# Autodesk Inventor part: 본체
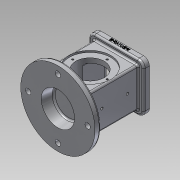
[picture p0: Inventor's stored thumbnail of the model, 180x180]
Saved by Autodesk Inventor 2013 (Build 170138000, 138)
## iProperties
Created: 2018-10
Part Number: 본체
Material: 알루미늄 6061
Document SubType Name: Modeling
Designer: hana-cad17
Density: 2.40731 g/cm^3
Mass: 877.844 g
Surface Area: 743.902 cm^2
Volume: 364.657 cm^3
Author: hana-cad17
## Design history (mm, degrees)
sketch "스케치1"
  geometry: C1 r 62.5 at (0, 0); 1 further point
  constraints: 1 centre point, 1 coincident
  dimensions: "d0" = 125 diameter of C1
extrude "돌출1" new body sketch "스케치1" distance "d1" = 10; taper "d2" = 0 deg
sketch "스케치2"
  geometry: L1 (37, 33)-(-37, 33); L2 (-37, 33)-(-37, -33); L3 (-37, -33)-(37, -33); L4 (37, -33)-(37, 33); L5 (37, 33)-(-37, -33); L6 (-37, 33)-(37, -33); C1 r 62.5 at (0, 0) reference
  constraints: 12 end point, 2 midpoint, 2 parallel, 1 horizontal, 1 perpendicular
  dimensions: "d5" = 66 distance of L3.end L1.start; "d6" = 74 distance of L1.start L1.end
extrude "돌출2" join sketch "스케치2" distance "d7" = 88; taper "d8" = 0 deg
sketch "스케치3"
  geometry: L1 (-46, 41)-(46, 41); L2 (46, 41)-(46, -41); L3 (46, -41)-(-46, -41); L4 (-46, -41)-(-46, 41); L5 (-46, 41)-(46, -41); L6 (46, 41)-(-46, -41); 1 further point
  constraints: 12 end point, 2 midpoint, 2 parallel, 1 horizontal, 1 perpendicular
  dimensions: "d9" = 92 distance of L2.end L3.end; "d10" = 82 distance of L1.end L2.end
extrude "돌출3" join sketch "스케치3" distance "d11" = 10; taper "d12" = 0 deg
sketch "스케치4"
  geometry: L1 (-25.5, -10)-(99.5, -10) reference; C1 r 35 at (37, 44); 1 further point
  constraints: 1 centre point, 1 vertical alignment
  dimensions: "d13" = 70 diameter of C1; "d14" = 54 distance from line of L1 C1.centre
extrude "돌출4" cut sketch "스케치4" distance "d15" = 3; taper "d16" = 0 deg
sketch "스케치5"
  geometry: C1 r 35 at (0, 0) reference; C2 r 24 at (0, 0); 1 further point
  constraints: 1 centre point, 1 coincident
  dimensions: "d17" = 48 diameter of C2
extrude "돌출5" cut sketch "스케치5" stored distance "d18" = 3; taper "d19" = 0 deg
sketch "스케치6" dims "d20" = 58
  geometry: C1 r 24 at (0, 0) reference; C2 r 35 at (0, 0) reference; 3 further points
  constraints: 2 vertical alignment, 1 coincident, 2 other
hole "구멍1" sketch "스케치6" at (0, 29) diameter "d21" = 3.242; stored, may be unused: countersink angle "d25" = 90 deg, drill point angle "d27" = 118 deg; dims "d22" = 4, "d23" = 4, "d24" = 2, "d26" = 6
sketch "스케치7"
  geometry: L1 (-26, 26)-(26, 26); L2 (26, 26)-(26, -26); L3 (26, -26)-(-26, -26); L4 (-26, -26)-(-26, 26); L5 (-26, 26)-(26, -26); L6 (26, 26)-(-26, -26); 1 further point
  constraints: 12 end point, 2 midpoint, 2 parallel, 1 horizontal, 1 perpendicular
  dimensions: "d31" = 52 distance of L2.end L3.end; "d32" = 52 distance of L1.end L2.end
extrude "돌출6" cut sketch "스케치7" distance "d33" = 8; taper "d34" = 0 deg
sketch "스케치8"
  geometry: L1 (-22, 22)-(22, 22); L2 (22, 22)-(22, -22); L3 (22, -22)-(-22, -22); L4 (-22, -22)-(-22, 22); L5 (-22, 22)-(22, -22); L6 (22, 22)-(-22, -22); 1 further point
  constraints: 12 end point, 2 midpoint, 2 parallel, 1 horizontal, 1 perpendicular
  dimensions: "d35" = 44 distance of L2.end L3.end; "d36" = 44 distance of L1.end L2.end
extrude "돌출7" cut sketch "스케치8" distance "d37" = 74; taper "d38" = 0 deg
sketch "스케치9"
  geometry: C1 r 62.5 at (0, 0) reference; C2 r 28 at (0, 0)
  constraints: 1 centre point, 1 coincident
  dimensions: "d39" = 56 diameter of C2
extrude "돌출8" cut sketch "스케치9" distance "d40" = 18; taper "d41" = 0 deg
feature "면 기울기1" dims angle "d42" = 10 deg
sketch "스케치10" dims "d43" = 100
  geometry: C1 r 62.5 at (0, 0) reference; C2 r 4.5 at (0, 50); 2 further points
  constraints: 2 coincident, 2 vertical alignment, 1 centre point, 2 other
  dimensions: "d44" = 9 diameter of C2
extrude "돌출9" cut sketch "스케치10" stored distance "d45" = 18; taper "d46" = 0 deg
fillet "모깎기1" dims "d50" = 10
sketch "스케치11"
  geometry: A1 r 10 centre (36, -31) between (36, -41) and (46, -31) reference; A2 r 10 centre (36, 31) between (46, 31) and (36, 41) reference; A3 r 10 centre (-36, 31) between (-36, 41) and (-46, 31) reference; A4 r 10 centre (-36, -31) between (-46, -31) and (-36, -41) reference; 5 further points
  constraints: 4 coincident
hole "구멍2" sketch "스케치11" at (-36, 31), (36, 31), (36, -31), (-36, -31) diameter "d51" = 3.242; stored, may be unused: countersink angle "d55" = 90 deg, drill point angle "d57" = 118 deg; dims "d52" = 4, "d53" = 4, "d54" = 2, "d56" = 6
node "작업 평면1"
sketch "스케치12"
  geometry: L1 (-46, 108)-(-46, 98) reference; L2 (-36, 108)-(36, 108) reference; 2 further points
  constraints: 1 other
  dimensions: "d59" = 46 distance from line of point (0, 104) L1; "d60" = 4 distance from line of point (0, 104) L2
feature "엠보싱1" sketch "스케치12" dims "d61" = 0.5, "d62" = 0
fillet "모깎기2" dims "d63" = 3
fillet "모깎기3" dims "d64" = 3
fillet "모깎기4" dims "d65" = 3
fillet "모깎기5" dims "d66" = 3
fillet "모깎기6" dims "d67" = 3
fillet "모깎기7" dims "d68" = 3
fillet "모깎기8" dims "d69" = 3
fillet "모깎기9" dims "d70" = 3
fillet "모깎기10" dims "d71" = 3
fillet "모깎기11" dims "d72" = 3
chamfer "모따기1" distance "d73" = 1; stored, may be unused: second distance "d74" = 2, angle "d75" = 45 deg
sketch "스케치13"
  geometry: L1 (-32.5, -13)-(92.5, -13) reference; 4 further points
  constraints: 2 vertical alignment, 1 midpoint
  dimensions: "d76" = 37 distance from line of point (30, 24) L1; "d77" = 43 distance of point (30, 67) point (30, 24)
hole "구멍3" sketch "스케치13" at (30, 24), (30, 67) diameter "d78" = 4.134; stored, may be unused: countersink angle "d82" = 90 deg, drill point angle "d84" = 118 deg; dims "d79" = 15, "d80" = 4, "d81" = 2, "d83" = 15
node "솔리드1"
pattern_circular "원형 패턴1" dims angle "d29" = 360 deg
mirror "대칭1"
pattern_circular "원형 패턴2" dims angle "d48" = 360 deg
other parameters: "d58" = 91.25
